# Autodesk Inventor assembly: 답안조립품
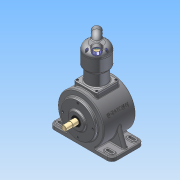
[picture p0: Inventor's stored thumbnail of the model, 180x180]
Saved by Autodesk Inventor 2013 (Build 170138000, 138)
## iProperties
Created: 2015-06
Part Number: 답안조립품
Document SubType Name: Assembly
Designer: ST3
Author: ST3
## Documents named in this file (15)
- C:\Users\ST3\Desktop\450605V1013\답안조립품.iam
- C:\Users\ST3\Desktop\450605V1013\1-본체.ipt
- C:\Users\ST3\Desktop\450605V1013\메인 크랭크 축-구동부.ipt
- C:\Users\ST3\Desktop\450605V1013\메인커버.ipt
- C:\Users\ST3\Desktop\450605V1013\베어링 6204.ipt
- C:\Users\ST3\Desktop\450605V1013\오일실.ipt
- C:\Users\ST3\Desktop\450605V1013\크랭크 서브축.ipt
- C:\Users\ST3\Desktop\450605V1013\베어링 NA 4902.ipt
- C:\Users\ST3\Desktop\450605V1013\피스톤 핀.ipt
- C:\Users\ST3\Desktop\450605V1013\피스톤.ipt
- C:\Users\ST3\Desktop\450605V1013\커넥팅 로드.ipt
- C:\Users\ST3\Desktop\450605V1013\실린더.ipt
- C:\Users\ST3\Desktop\450605V1013\실린더헤드.ipt
- C:\Users\ST3\Desktop\450605V1013\M5x0.8.ipt
- C:\Users\ST3\Desktop\450605V1013\M4x0.7.ipt
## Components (15 placed, 5 different names)
1. 1-본체:1
2. 피스톤 핀:1
3. 피스톤:1
4. M5x0.8:1 — 각도:1
5. M5x0.8:2
6. M5x0.8:3
7. M5x0.8:4
8. M4x0.7:1 — 각도:2
9. M4x0.7:2
10. M4x0.7:3
11. M4x0.7:4
12. M4x0.7:5 — 각도:3
13. M4x0.7:6
14. M4x0.7:7
15. M4x0.7:8
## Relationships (3: Angle 3)
- 각도:1 [Angle]: M5x0.8:1
- 각도:2 [Angle]: M4x0.7:1
- 각도:3 [Angle]: M4x0.7:5
